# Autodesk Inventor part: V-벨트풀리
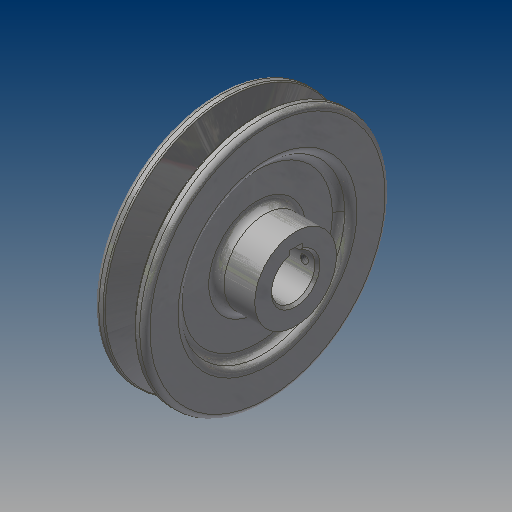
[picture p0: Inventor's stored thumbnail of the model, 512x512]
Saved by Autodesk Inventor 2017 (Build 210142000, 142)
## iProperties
Created: 2015-09
Part Number: V-벨트풀리
Material: 강철, 연강
Document SubType Name: Modeling
Designer: mduedu
Density: 7.86 g/cm^3
Mass: 779.014 g
Surface Area: 277.465 cm^2
Volume: 99.1112 cm^3
Appearance: 강철
Author: mduedu
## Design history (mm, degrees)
sketch "스케치1"
  geometry: L1 (-10, 0)-(10, 0); L2 (-10, 0)-(-10, 48); L3 (-10, 48)-(-5.976, 48); L4 (-5.976, 48)-(-2.154, 35.5); L5 (-2.154, 35.5)-(2.154, 35.5); L6 (2.154, 35.5)-(5.976, 48); L7 (5.976, 48)-(10, 48); L8 (10, 48)-(10, 0); L9 (0, 0)-(0, 35.5); L10 (-10, 43.5)-(10, 43.5); 3 further points
  constraints: 20 end point, 6 point on line, 3 perpendicular, 2 midpoint, 2 parallel, 2 symmetric about line, 1 coincident, 1 collinear, 1 equal length, 1 horizontal, 1 vertical, 1 vertical alignment
  dimensions: "d0" = 20 distance between parallel lines of L8 L2; "d2" = 96 diameter of L3 L1; "d3" = 87 diameter of L10 L1; "d4" = 4.5 distance between parallel lines of L10 L3 (derived); "d5" = 8 distance between parallel lines of L5 L10; "d6" = 9.2 distance of point (4.6, 43.5) point (-4.6, 43.5); "d7" = 34 deg angle of L6 L4
revolve "회전1" sketch "스케치1" stored, may be unused: angle "d8" = 90 deg
sketch "스케치2"
  geometry: C1 r 16 at (0, 0); 1 further point
  constraints: 1 centre point, 1 coincident
  dimensions: "d9" = 32 diameter of C1
extrude "돌출1" join sketch "스케치2" distance "d10" = 11; taper "d11" = 0 deg
fillet "모깎기1" dims "d12" = 1, "d13" = 0.5, "d14" = 2
sketch "스케치3"
  geometry: C1 r 16 at (0, 0) reference; C2 r 32 at (0, 0); 1 further point
  constraints: 1 centre point, 1 coincident
  dimensions: "d15" = 64 diameter of C2
extrude "돌출2" cut sketch "스케치3" distance "d16" = 4; taper "d17" = 0 deg
fillet "모깎기2" dims "d18" = 3
fillet "모깎기3" dims "d19" = 3
fillet "모깎기4" dims "d20" = 3
sketch "스케치4"
  geometry: C1 r 8.5 at (0, 0); 1 further point
  constraints: 1 centre point, 1 coincident
  dimensions: "d21" = 17 diameter of C1
extrude "돌출3" cut sketch "스케치4" stored distance "d22" = 4; taper "d23" = 0 deg
sketch "스케치5"
  geometry: L1 (-2.5, 8.124)-(2.5, 8.124); L2 (2.5, 8.124)-(2.5, 10.8); L3 (2.5, 10.8)-(-2.5, 10.8); L4 (-2.5, 10.8)-(-2.5, 8.124); A1 r 8.5 centre (0, 0) between (-2.5, 8.124) and (2.5, 8.124) reference; 2 further points
  constraints: 8 end point, 3 point on circle, 2 parallel, 1 horizontal, 1 perpendicular, 1 vertical alignment
  dimensions: "d24" = 5 distance of L2.end L3.end; "d26" = 19.3 distance from line of L3 point (0, -8.5)
extrude "돌출4" cut sketch "스케치5" stored distance "d27" = 4; taper "d28" = 0 deg
chamfer "모따기1" distance "d29" = 1; stored, may be unused: second distance "d30" = 2, angle "d31" = 45 deg
node "작업 평면1"
sketch "스케치6"
  geometry: L1 (-11, 16)-(-11, -16) reference; 2 further points
  constraints: 1 horizontal alignment
  dimensions: "d32" = 5 distance from line of point (-6, 0) L1
hole "구멍1" sketch "스케치6" at (-6, 0) diameter "d33" = 3.242; stored, may be unused: countersink angle "d37" = 90 deg, drill point angle "d39" = 118 deg; dims "d34" = 6, "d35" = 4, "d36" = 2, "d38" = 8
node "솔리드1"
mirror "대칭1"
